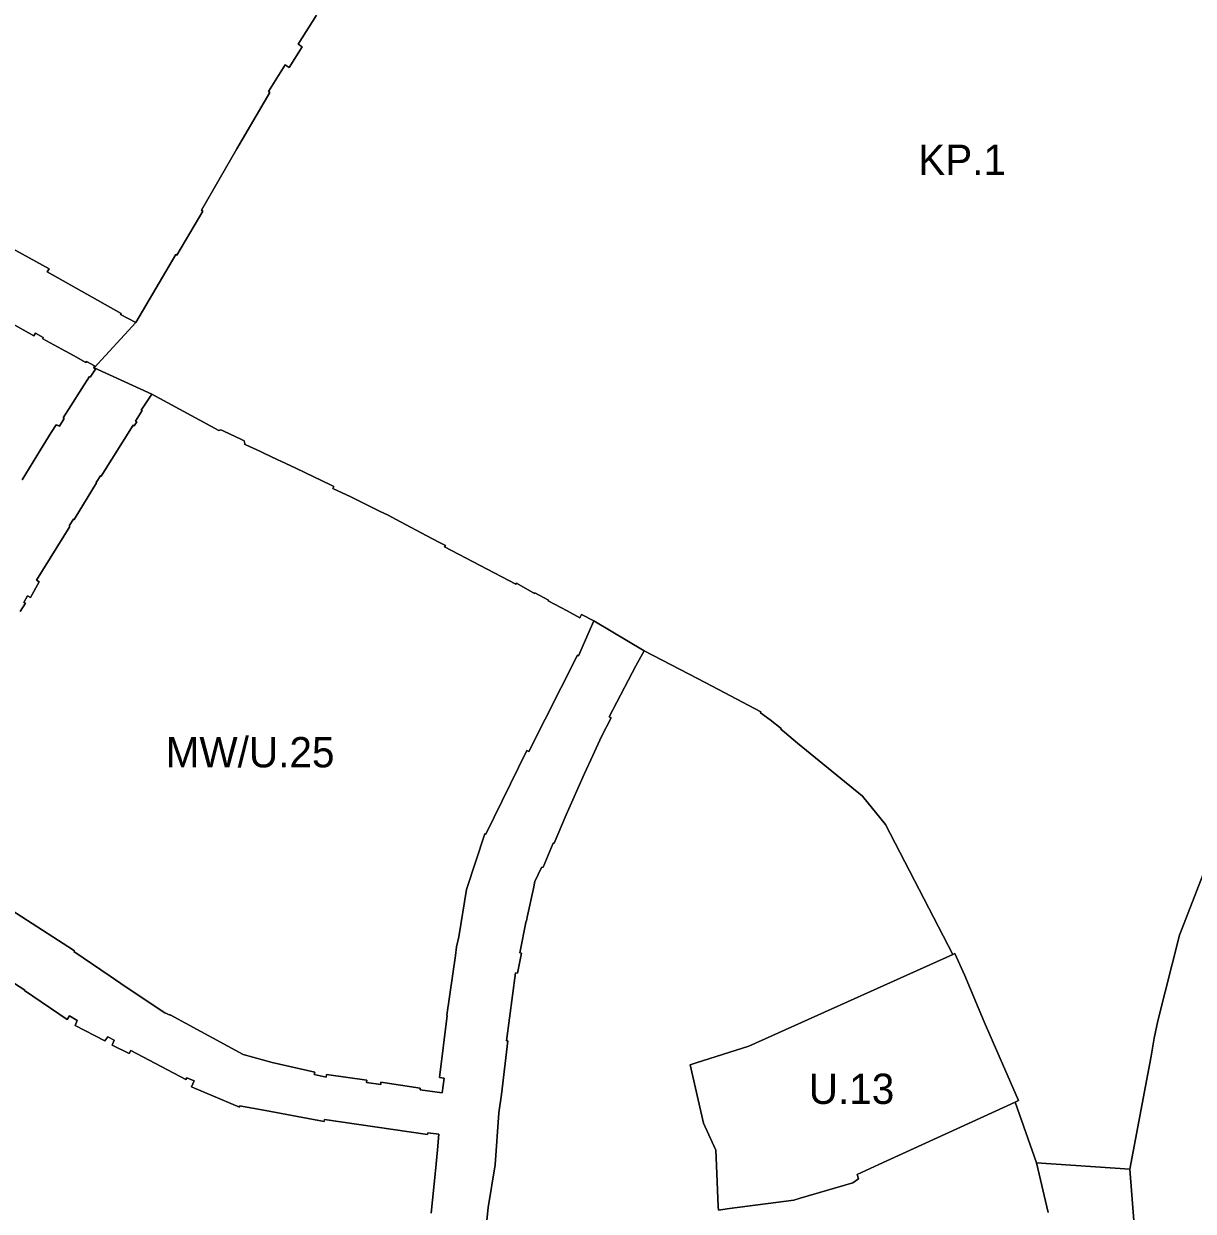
# Model space of a CAD drawing. Extents: x 7423367 to 7424726, y 5546744 to 5548391.
# Drawn here: x 7423762.4 to 7423955.4, y 5547645 to 5547840.8 of the extents above; entities that cross this region are included whole.
import ezdxf

# ---------------------------------------------------------------- set-up
doc = ezdxf.new("R2010")
doc.units = 0
doc.layers.add('linie_rozgraniczajace', color=7, linetype='Continuous')
doc.layers.add('oznaczenia_przeznaczen', color=7, linetype='Continuous')

msp = doc.modelspace()

# ---------------------------------------------------------------- linework, layer by layer
at = {"layer": 'linie_rozgraniczajace'}
for points in [[(7423810.74, 5547842.25), (7423807.72, 5547837.46), (7423808.41, 5547837.02), (7423806.25, 5547833.61), (7423805.6, 5547834.03), (7423802.84, 5547829.63), (7423803.05, 5547829.49), (7423797.62, 5547820.18), (7423791.77, 5547810.05), (7423792.01, 5547809.89), (7423787.71, 5547802.65), (7423787.54, 5547802.74), (7423780.92, 5547791.57), (7423778.43, 5547792.85), (7423778.52, 5547793.01), (7423766.33, 5547799.89), (7423766.63, 5547800.41), (7423737.4, 5547816.48)], [(7423957.42, 5547701.56), (7423953.17, 5547690.5), (7423949.6, 5547676.37), (7423948.98, 5547673.5), (7423948.5, 5547670.54), (7423944.94, 5547651.91), (7423929.54, 5547652.96), (7423926.01, 5547662.96), (7423926.59, 5547663.22), (7423920.92, 5547676.18), (7423917.65, 5547683.94), (7423916.1, 5547687.45), (7423915.74, 5547687.29), (7423904.66, 5547708.72), (7423900.84, 5547713.44), (7423890.09, 5547722.15), (7423887.95, 5547723.96), (7423887.35, 5547724.47), (7423887.42, 5547724.56), (7423885.61, 5547725.99), (7423884.02, 5547727.19), (7423884.09, 5547727.31), (7423876.01, 5547731.59), (7423873.6, 5547732.82), (7423864.81, 5547737.39), (7423856.5, 5547742.34), (7423854.46, 5547743.38), (7423854.19, 5547742.85), (7423852.09, 5547743.98), (7423848.98, 5547745.62), (7423849.04, 5547745.75), (7423846.78, 5547746.94), (7423846.72, 5547746.83), (7423843.73, 5547748.55), (7423843.66, 5547748.39), (7423831.85, 5547754.52), (7423832.01, 5547754.77), (7423830.91, 5547755.33), (7423828.94, 5547756.36), (7423824.6, 5547758.65), (7423822.46, 5547759.8), (7423821.27, 5547760.39), (7423816.41, 5547762.78), (7423813.47, 5547764.18), (7423813.6, 5547764.52), (7423813.15, 5547764.74), (7423807.32, 5547767.52), (7423804.89, 5547768.66), (7423804.35, 5547768.92), (7423801.96, 5547770.05), (7423801.49, 5547770.28), (7423799.07, 5547771.39), (7423798.88, 5547771.48), (7423798.92, 5547771.6), (7423798.84, 5547772.03), (7423798.36, 5547772.26), (7423795.46, 5547773.63), (7423794.97, 5547773.84), (7423794.61, 5547773.72), (7423783.59, 5547779.73), (7423774.06, 5547784.06), (7423780.92, 5547791.57), (7423787.54, 5547802.74), (7423787.71, 5547802.65), (7423792.01, 5547809.89), (7423791.77, 5547810.05), (7423797.62, 5547820.18), (7423803.05, 5547829.49), (7423802.84, 5547829.63), (7423805.6, 5547834.03), (7423806.25, 5547833.61), (7423808.41, 5547837.02), (7423807.72, 5547837.46), (7423810.74, 5547842.25)], [(7423737.4, 5547816.48), (7423766.63, 5547800.41), (7423766.33, 5547799.89), (7423778.52, 5547793.01), (7423778.43, 5547792.85), (7423780.92, 5547791.57), (7423774.06, 5547784.06), (7423773.99, 5547784.13), (7423774.12, 5547784.41), (7423772.78, 5547785.13), (7423772.69, 5547784.97), (7423770.63, 5547786.1), (7423767.99, 5547787.56), (7423765.59, 5547788.88), (7423765.67, 5547789.06), (7423764.37, 5547789.77), (7423764.13, 5547789.34), (7423737.82, 5547804.09)], [(7423737.82, 5547804.09), (7423764.13, 5547789.34), (7423764.37, 5547789.77), (7423765.67, 5547789.06), (7423765.59, 5547788.88), (7423767.99, 5547787.56), (7423770.63, 5547786.1), (7423772.69, 5547784.97), (7423772.78, 5547785.13), (7423774.12, 5547784.41), (7423773.99, 5547784.13), (7423774.06, 5547784.06), (7423774.03, 5547784), (7423774.26, 5547783.86), (7423773.4, 5547782.54), (7423773.27, 5547782.63), (7423772.02, 5547780.67), (7423770.2, 5547777.8), (7423768.95, 5547775.83), (7423769.13, 5547775.72), (7423768.32, 5547774.43), (7423768.02, 5547774.62), (7423767.99, 5547774.57), (7423767.8, 5547774.69), (7423766.98, 5547773.4), (7423765.23, 5547770.52), (7423762.21, 5547765.59)], [(7423762.21, 5547765.59), (7423765.23, 5547770.52), (7423766.98, 5547773.4), (7423767.8, 5547774.69), (7423767.99, 5547774.57), (7423768.02, 5547774.62), (7423768.32, 5547774.43), (7423769.13, 5547775.72), (7423768.95, 5547775.83), (7423770.2, 5547777.8), (7423772.02, 5547780.67), (7423773.27, 5547782.63), (7423773.4, 5547782.54), (7423774.26, 5547783.86), (7423774.03, 5547784), (7423774.06, 5547784.06), (7423783.59, 5547779.73), (7423781.83, 5547777.11), (7423781.96, 5547777.03), (7423780.88, 5547775.27), (7423781.08, 5547775.15), (7423780.67, 5547774.51), (7423780.48, 5547774.62), (7423775.22, 5547766.2), (7423775.1, 5547766.27), (7423774.37, 5547765.13), (7423774.47, 5547765.08), (7423770.75, 5547759.06), (7423770.63, 5547759.12), (7423769.92, 5547757.99), (7423770.07, 5547757.92), (7423764.53, 5547749.06), (7423765.01, 5547748.77), (7423763.57, 5547746.2), (7423763.07, 5547746.48), (7423762.47, 5547745.38), (7423762.72, 5547745.26), (7423761.85, 5547743.87)], [(7423761.85, 5547743.87), (7423762.72, 5547745.26), (7423762.47, 5547745.38), (7423763.07, 5547746.48), (7423763.57, 5547746.2), (7423765.01, 5547748.77), (7423764.53, 5547749.06), (7423770.07, 5547757.92), (7423769.92, 5547757.99), (7423770.63, 5547759.12), (7423770.75, 5547759.06), (7423774.47, 5547765.08), (7423774.37, 5547765.13), (7423775.1, 5547766.27), (7423775.22, 5547766.2), (7423780.48, 5547774.62), (7423780.67, 5547774.51), (7423781.08, 5547775.15), (7423780.88, 5547775.27), (7423781.96, 5547777.03), (7423781.83, 5547777.11), (7423783.59, 5547779.73), (7423794.61, 5547773.72), (7423794.97, 5547773.84), (7423795.46, 5547773.63), (7423798.36, 5547772.26), (7423798.84, 5547772.03), (7423798.92, 5547771.6), (7423798.88, 5547771.48), (7423799.07, 5547771.39), (7423801.49, 5547770.28), (7423801.96, 5547770.05), (7423804.35, 5547768.92), (7423804.89, 5547768.66), (7423807.32, 5547767.52), (7423813.15, 5547764.74), (7423813.6, 5547764.52), (7423813.47, 5547764.18), (7423816.41, 5547762.78), (7423821.27, 5547760.39), (7423822.46, 5547759.8), (7423824.6, 5547758.65), (7423828.94, 5547756.36), (7423830.91, 5547755.33), (7423832.01, 5547754.77), (7423831.85, 5547754.52), (7423843.66, 5547748.39), (7423843.73, 5547748.55), (7423846.72, 5547746.83), (7423846.78, 5547746.94), (7423849.04, 5547745.75), (7423848.98, 5547745.62), (7423852.09, 5547743.98), (7423854.19, 5547742.85), (7423854.46, 5547743.38), (7423856.5, 5547742.34), (7423853.96, 5547736.58), (7423853.79, 5547736.65), (7423845.79, 5547720.8), (7423845.43, 5547720.96), (7423838.71, 5547707.13), (7423838.51, 5547707.21), (7423835.52, 5547698.05), (7423834.22, 5547690.24), (7423833.87, 5547688.59), (7423833.67, 5547687.12), (7423832.23, 5547677.31), (7423832.29, 5547677.26), (7423831.04, 5547667.03), (7423831.82, 5547666.92), (7423831.49, 5547664.46), (7423827.83, 5547664.96), (7423827.87, 5547665.26), (7423821.39, 5547666.25), (7423821.34, 5547665.85), (7423818.99, 5547666.18), (7423819.08, 5547666.57), (7423812.41, 5547667.53), (7423812.32, 5547667.09), (7423810.37, 5547667.49), (7423810.45, 5547667.9), (7423803.44, 5547669.49), (7423798.64, 5547670.82), (7423786.62, 5547677.34), (7423786.59, 5547677.28), (7423785.74, 5547677.68), (7423779.32, 5547681.89), (7423776.7, 5547683.72), (7423770.72, 5547687.8), (7423770.8, 5547687.91), (7423770.65, 5547688.01), (7423750.15, 5547701.19)], [(7423750.15, 5547701.19), (7423770.65, 5547688.01), (7423770.8, 5547687.91), (7423770.72, 5547687.8), (7423776.7, 5547683.72), (7423779.32, 5547681.89), (7423785.74, 5547677.68), (7423786.59, 5547677.28), (7423786.62, 5547677.34), (7423798.64, 5547670.82), (7423803.44, 5547669.49), (7423810.45, 5547667.9), (7423810.37, 5547667.49), (7423812.32, 5547667.09), (7423812.41, 5547667.53), (7423819.08, 5547666.57), (7423818.99, 5547666.18), (7423821.34, 5547665.85), (7423821.39, 5547666.25), (7423827.87, 5547665.26), (7423827.83, 5547664.96), (7423831.49, 5547664.46), (7423831.82, 5547666.92), (7423831.04, 5547667.03), (7423832.29, 5547677.26), (7423832.23, 5547677.31), (7423833.67, 5547687.12), (7423833.87, 5547688.59), (7423834.22, 5547690.24), (7423835.52, 5547698.05), (7423838.51, 5547707.21), (7423838.71, 5547707.13), (7423845.43, 5547720.96), (7423845.79, 5547720.8), (7423853.79, 5547736.65), (7423853.96, 5547736.58), (7423856.5, 5547742.34), (7423864.81, 5547737.39), (7423863.42, 5547734.94), (7423859.04, 5547726.53), (7423859.39, 5547726.36), (7423857.78, 5547723.26), (7423856.36, 5547720.11), (7423854.96, 5547717.15), (7423851.93, 5547710.34), (7423849.98, 5547705.64), (7423849.82, 5547705.65), (7423848.14, 5547701.72), (7423847.85, 5547701.64), (7423846.79, 5547699.33), (7423846.53, 5547698.18), (7423845.5, 5547693.48), (7423845.38, 5547692.82), (7423845.33, 5547692.83), (7423844.31, 5547687.58), (7423844.56, 5547687.52), (7423843.9, 5547684.22), (7423843.61, 5547684.3), (7423842.11, 5547673.05), (7423842.34, 5547673.04), (7423841.25, 5547664.22), (7423840.85, 5547661.18), (7423840.21, 5547652.61), (7423839.09, 5547645.58), (7423838.86, 5547643.41)], [(7423838.86, 5547643.41), (7423839.09, 5547645.58), (7423840.21, 5547652.61), (7423840.85, 5547661.18), (7423841.25, 5547664.22), (7423842.34, 5547673.04), (7423842.11, 5547673.05), (7423843.61, 5547684.3), (7423843.9, 5547684.22), (7423844.56, 5547687.52), (7423844.31, 5547687.58), (7423845.33, 5547692.83), (7423845.38, 5547692.82), (7423845.5, 5547693.48), (7423846.53, 5547698.18), (7423846.79, 5547699.33), (7423847.85, 5547701.64), (7423848.14, 5547701.72), (7423849.82, 5547705.65), (7423849.98, 5547705.64), (7423851.93, 5547710.34), (7423854.96, 5547717.15), (7423856.36, 5547720.11), (7423857.78, 5547723.26), (7423859.39, 5547726.36), (7423859.04, 5547726.53), (7423863.42, 5547734.94), (7423864.81, 5547737.39), (7423873.6, 5547732.82), (7423876.01, 5547731.59), (7423884.09, 5547727.31), (7423884.02, 5547727.19), (7423885.61, 5547725.99), (7423887.42, 5547724.56), (7423887.35, 5547724.47), (7423887.95, 5547723.96), (7423890.09, 5547722.15), (7423900.84, 5547713.44), (7423904.66, 5547708.72), (7423915.74, 5547687.29), (7423882.1, 5547672.16), (7423873.37, 5547669.41), (7423872.42, 5547669.11), (7423874.62, 5547659.46), (7423876.64, 5547655.05), (7423876.75, 5547652.52), (7423877.04, 5547645.75), (7423877.07, 5547645.15), (7423878.89, 5547645.39), (7423889.49, 5547646.79), (7423890.56, 5547647.1), (7423899.26, 5547649.64), (7423900.2, 5547650.31), (7423899.99, 5547651.04), (7423903.56, 5547652.66), (7423926.01, 5547662.96), (7423929.54, 5547652.96), (7423931.48, 5547644.77)], [(7423956.13, 5547549.82), (7423953.67, 5547549.49), (7423952.85, 5547559.12), (7423952.31, 5547566.09), (7423950.87, 5547581.59), (7423950.35, 5547587.25), (7423949.72, 5547594), (7423949.1, 5547600.91), (7423948.68, 5547607.79), (7423948.13, 5547613.84), (7423947.24, 5547623.76), (7423946.05, 5547637.74), (7423944.94, 5547651.91), (7423948.5, 5547670.54), (7423948.98, 5547673.5), (7423949.6, 5547676.37), (7423953.17, 5547690.5), (7423957.42, 5547701.56)], [(7423752.86, 5547687.68), (7423762.6, 5547681.43), (7423762.56, 5547681.38), (7423769.62, 5547676.56), (7423770.01, 5547677.2), (7423771.28, 5547676.42), (7423770.91, 5547675.61), (7423775.85, 5547673.07), (7423776.33, 5547673.7), (7423777.39, 5547673.16), (7423777.02, 5547672.37), (7423779.84, 5547670.99), (7423780.1, 5547671.46), (7423789.21, 5547666.69), (7423789.33, 5547666.94), (7423790.54, 5547666.44), (7423790.14, 5547665.47), (7423790.63, 5547665.27), (7423793.38, 5547664.12), (7423798.02, 5547662.13), (7423798.07, 5547662.36), (7423802.34, 5547661.58), (7423812.01, 5547659.73), (7423812.07, 5547660.11), (7423829.06, 5547657.59), (7423829.11, 5547657.89), (7423830.93, 5547657.68), (7423830.71, 5547655.11), (7423830.38, 5547651.64), (7423829.69, 5547644.61)], [(7423829.69, 5547644.61), (7423830.38, 5547651.64), (7423830.71, 5547655.11), (7423830.93, 5547657.68), (7423829.11, 5547657.89), (7423829.06, 5547657.59), (7423812.07, 5547660.11), (7423812.01, 5547659.73), (7423802.34, 5547661.58), (7423798.07, 5547662.36), (7423798.02, 5547662.13), (7423793.38, 5547664.12), (7423790.63, 5547665.27), (7423790.14, 5547665.47), (7423790.54, 5547666.44), (7423789.33, 5547666.94), (7423789.21, 5547666.69), (7423780.1, 5547671.46), (7423779.84, 5547670.99), (7423777.02, 5547672.37), (7423777.39, 5547673.16), (7423776.33, 5547673.7), (7423775.85, 5547673.07), (7423770.91, 5547675.61), (7423771.28, 5547676.42), (7423770.01, 5547677.2), (7423769.62, 5547676.56), (7423762.56, 5547681.38), (7423762.6, 5547681.43), (7423752.86, 5547687.68)], [(7423931.48, 5547644.77), (7423929.54, 5547652.96), (7423944.94, 5547651.91), (7423946.05, 5547637.74)]]:
    msp.add_lwpolyline(points, dxfattribs=at)
msp.add_lwpolyline([(7423872.42, 5547669.11), (7423873.37, 5547669.41), (7423882.1, 5547672.16), (7423915.74, 5547687.29), (7423916.1, 5547687.45), (7423917.65, 5547683.94), (7423920.92, 5547676.18), (7423926.59, 5547663.22), (7423926.01, 5547662.96), (7423903.56, 5547652.66), (7423899.99, 5547651.04), (7423900.2, 5547650.31), (7423899.26, 5547649.64), (7423890.56, 5547647.1), (7423889.49, 5547646.79), (7423878.89, 5547645.39), (7423877.07, 5547645.15), (7423877.04, 5547645.75), (7423876.75, 5547652.52), (7423876.64, 5547655.05), (7423874.62, 5547659.46)], close=True, dxfattribs=at)

# ---------------------------------------------------------------- texts
at = {"layer": 'oznaczenia_przeznaczen'}
for s, p in [('KP.1', (7423910.03, 5547815.89)), ('MW/U.25', (7423785.86, 5547718.17)), ('U.13', (7423891.97, 5547662.65))]:
    msp.add_text(s, height=5, dxfattribs=at).set_placement(p)

doc.saveas('drawing.dxf')
